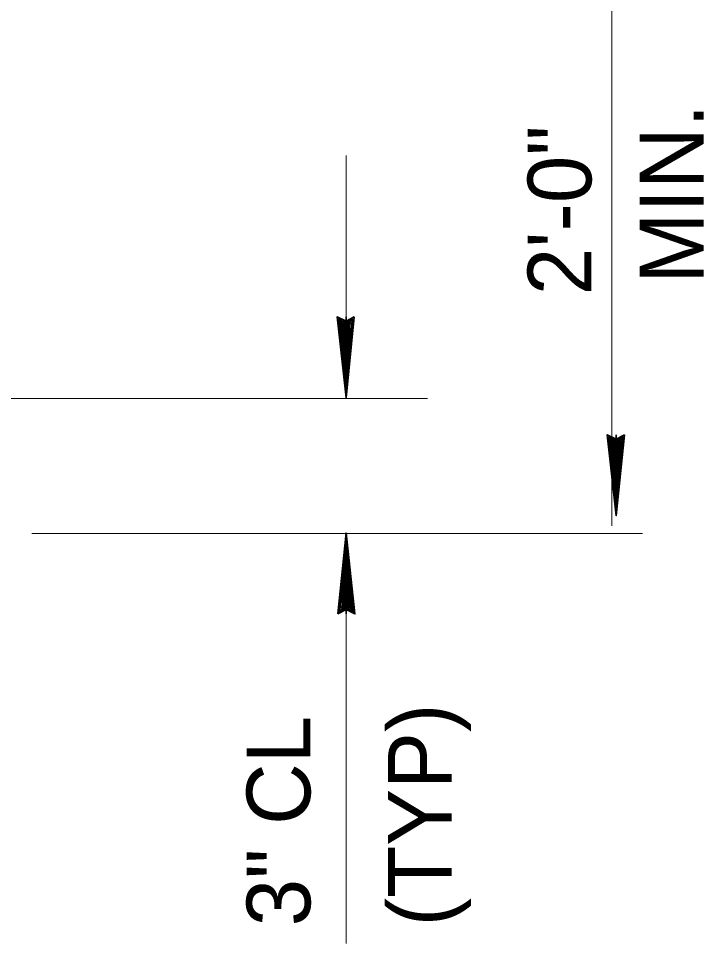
# Model space of a CAD drawing. Extents: x 14.14 to 17.34, y -1.61 to 0.38.
# Drawn here: x 16.5014 to 16.591, y -0.0688 to 0.0521 of the extents above; entities that cross this region are included whole.
import ezdxf

# ---------------------------------------------------------------- set-up
doc = ezdxf.new("R2010")
doc.units = 0
doc.header["$LTSCALE"] = 0.0033
doc.layers.add('1', color=7, linetype='Continuous', lineweight=40)

msp = doc.modelspace()

# ---------------------------------------------------------------- linework, layer by layer
at = {"layer": '1', "lineweight": 13}
for p, q in [((16.579, 0.069083), (16.579, -0.01425)), ((16.54425, 0.002417), (16.54425, 0.034167)), ((16.484917, 0.002417), (16.554917, 0.002417)), ((16.503167, -0.01525), (16.583, -0.01525)), ((16.54425, -0.068833), (16.54425, -0.017))]:
    msp.add_line(p, q, dxfattribs=at)
at = {"layer": '1', "lineweight": 35}
for p, q in [((16.543167, 0.012833), (16.544, 0.0055)), ((16.543333, 0.012833), (16.544083, 0.0055)), ((16.543417, 0.012833), (16.54425, 0.0055)), ((16.543583, 0.012917), (16.544333, 0.005583)), ((16.545083, 0.012833), (16.544083, 0.005)), ((16.54425, 0.013083), (16.54425, 0.0025)), ((16.545083, 0.012833), (16.54425, 0.005)), ((16.54525, 0.012833), (16.544333, 0.005)), ((16.54525, 0.012833), (16.544333, 0.005)), ((16.545167, 0.012833), (16.544333, 0.005)), ((16.579583, -0.002333), (16.579583, -0.012917)), ((16.5785, -0.002583), (16.579333, -0.009917)), ((16.578667, -0.002583), (16.579417, -0.009917)), ((16.57875, -0.002583), (16.579583, -0.009917)), ((16.578917, -0.0025), (16.579667, -0.009833)), ((16.580417, -0.002583), (16.579417, -0.010417)), ((16.580417, -0.002583), (16.579583, -0.010417)), ((16.580583, -0.002583), (16.579667, -0.010417)), ((16.580583, -0.002583), (16.579667, -0.010417)), ((16.5805, -0.002583), (16.579667, -0.010417)), ((16.54425, -0.02575), (16.54425, -0.015167)), ((16.54325, -0.0255), (16.544167, -0.017667)), ((16.54325, -0.0255), (16.544167, -0.017667)), ((16.543333, -0.0255), (16.544167, -0.017667)), ((16.543417, -0.0255), (16.54425, -0.017667)), ((16.543417, -0.0255), (16.544417, -0.017667)), ((16.544917, -0.025583), (16.544167, -0.01825)), ((16.545083, -0.0255), (16.54425, -0.018167)), ((16.545167, -0.0255), (16.544417, -0.018167)), ((16.545333, -0.0255), (16.5445, -0.018167))]:
    msp.add_line(p, q, dxfattribs=at)
for points in [[(16.545333, 0.013083), (16.54425, 0.0025), (16.543083, 0.013083), (16.54425, 0.0125)], [(16.544333, 0.012333), (16.544417, 0.007667), (16.544333, 0.007667), (16.544333, 0.008583), (16.544417, 0.012333), (16.5445, 0.009333), (16.544583, 0.0125), (16.544667, 0.01025), (16.54475, 0.0125), (16.5445, 0.009), (16.544333, 0.004333), (16.544083, 0.00525), (16.544083, 0.004), (16.544083, 0.012333), (16.543917, 0.009917), (16.543917, 0.0125), (16.544333, 0.007167), (16.543667, 0.0125)], [(16.580667, -0.002333), (16.579583, -0.012917), (16.578417, -0.002333), (16.579583, -0.002917)], [(16.579667, -0.003083), (16.57975, -0.00775), (16.579667, -0.00775), (16.579667, -0.006833), (16.57975, -0.003083), (16.579833, -0.006083), (16.579917, -0.002917), (16.58, -0.005167), (16.580083, -0.002917), (16.579833, -0.006417), (16.579667, -0.011083), (16.579417, -0.010167), (16.579417, -0.011417), (16.579417, -0.003083), (16.57925, -0.0055), (16.57925, -0.002917), (16.579667, -0.00825), (16.579, -0.002917)], [(16.543167, -0.02575), (16.54425, -0.015167), (16.545417, -0.02575), (16.54425, -0.025167)], [(16.544167, -0.025), (16.544083, -0.020333), (16.544167, -0.020333), (16.544167, -0.02125), (16.544083, -0.025), (16.544, -0.022), (16.543917, -0.025167), (16.543833, -0.022917), (16.54375, -0.025167), (16.544, -0.021667), (16.544167, -0.017), (16.544417, -0.017917), (16.544417, -0.016667), (16.544417, -0.025), (16.544583, -0.022583), (16.544583, -0.025167), (16.544167, -0.019833), (16.544833, -0.025167)]]:
    msp.add_lwpolyline(points, close=True, dxfattribs=at)
for points in [[(16.544333, 0.012333), (16.545083, 0.01275), (16.544833, 0.0125), (16.5445, 0.012333), (16.544583, 0.012083), (16.544917, 0.01225), (16.544167, 0.012417), (16.543667, 0.012583), (16.54325, 0.012833)], [(16.579667, -0.003083), (16.580417, -0.002667), (16.580167, -0.002917), (16.579833, -0.003083), (16.579917, -0.003333), (16.58025, -0.003167), (16.5795, -0.003), (16.579, -0.002833), (16.578583, -0.002583)], [(16.544167, -0.025), (16.543417, -0.025417), (16.543667, -0.025167), (16.544, -0.025), (16.543917, -0.02475), (16.543583, -0.024917), (16.544333, -0.025083), (16.544833, -0.02525), (16.54525, -0.0255)]]:
    msp.add_lwpolyline(points, dxfattribs=at)

# ---------------------------------------------------------------- texts
at = {"layer": '1'}
for s, height, p in [('MIN.', 0.008334, (16.591, 0.017417)), ('2\'-0"', 0.008333, (16.576333, 0.015917)), ('(TYP)', 0.008334, (16.558083, -0.066583)), ('3" CL', 0.008334, (16.539583, -0.066583))]:
    msp.add_text(s, height=height, rotation=90, dxfattribs=at).set_placement(p)

doc.saveas('drawing.dxf')
